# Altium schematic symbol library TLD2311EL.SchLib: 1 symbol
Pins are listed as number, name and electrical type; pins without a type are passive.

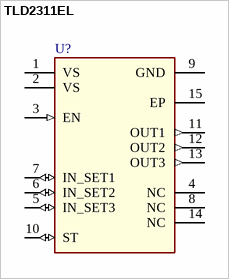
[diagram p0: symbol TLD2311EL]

## TLD2311EL
designator U?  (value not drawn)
Basic LED Driver, 3 Channel High Side Current Source; Manufacturer: Infineon Technologies
footprint SOP65P600X170-15N
pins: 1 VS (power) "Supply Voltage", 2 VS (power) "Supply Voltage", 3 EN (in) "Enable Pin", 4 NC "Not Connected", 5 IN_SET3 (io) "Input / SET Pin 3", 6 IN_SET2 (io) "Input / SET Pin 2", 7 IN_SET1 (io) "Input / SET Pin 1", 8 NC "Not Connected", 9 GND (power) "Ground", 10 ST (io) "Status Pin", 11 OUT1 (out) "Output 1", 12 OUT2 (out) "Output 2", 13 OUT3 (out) "Output 3", 14 NC "Not Connected", 15 EP (power) "Exposed Pad"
